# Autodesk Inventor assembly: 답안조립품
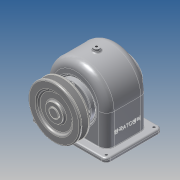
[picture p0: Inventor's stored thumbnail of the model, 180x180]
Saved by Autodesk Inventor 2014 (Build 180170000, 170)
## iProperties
Created: 2016-01
Part Number: 답안조립품
Document SubType Name: Assembly
Designer: user
Author: user
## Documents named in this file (14)
- C:\Users\user\Desktop\460106V1007\답안조립품.iam
- C:\Users\user\Desktop\460106V1007\본체.ipt
- C:\Users\user\Desktop\460106V1007\뒤커버.ipt
- C:\Users\user\Desktop\460106V1007\앞커버.ipt
- C:\Users\user\Desktop\460106V1007\축.ipt
- C:\Users\user\Desktop\460106V1007\키 - 6 x 6 x 22.ipt
- C:\Users\user\Desktop\460106V1007\볼트 M3 x 8.ipt
- C:\Users\user\Desktop\460106V1007\볼트 M3 x 10.ipt
- C:\Users\user\Desktop\460106V1007\키 - 5 x 5 x 18.ipt
- C:\Users\user\Desktop\460106V1007\오일씰 28 40 8.ipt
- C:\Users\user\Desktop\460106V1007\베어링 6203.ipt
- C:\Users\user\Desktop\460106V1007\스퍼기어.ipt
- C:\Users\user\Desktop\460106V1007\V-벨트풀리.ipt
- C:\Users\user\Desktop\460106V1007\멈춤나사 - M4x10.ipt
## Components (9 placed, 3 different names)
1. V-벨트풀리:1 — Insert:13, Mate:6, Tangent:1, Angle:1
2. ISO 4762 M3 x 8:1 — Insert:5
3. ISO 4762 M3 x 8:2
4. ISO 4762 M3 x 8:3
5. ISO 4762 M3 x 8:4
6. ISO 4762 M3 x 10:1 — Insert:4
7. ISO 4762 M3 x 10:2
8. ISO 4762 M3 x 10:3
9. ISO 4762 M3 x 10:4
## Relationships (6: Insert 3, Mate 1, Tangent 1, Angle 1)
- Insert:4: ISO 4762 M3 x 10:1
- Insert:5: ISO 4762 M3 x 8:1
- Insert:13: V-벨트풀리:1
- Mate:6: V-벨트풀리:1
- Tangent:1: V-벨트풀리:1
- Angle:1: V-벨트풀리:1
